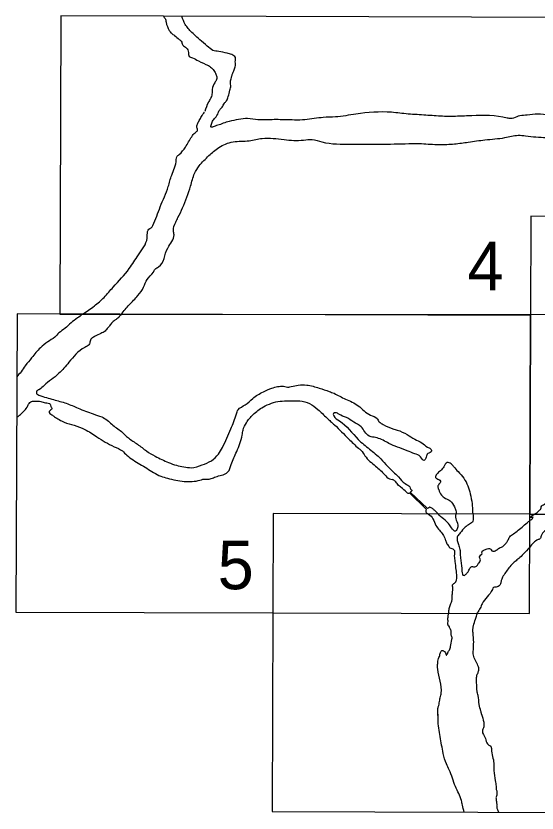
# Model space of a CAD drawing. Extents: x 3148686 to 3186545, y 916144 to 941516.
# Drawn here: x 3173455 to 3174711, y 918387 to 920308 of the extents above; entities that cross this region are included whole.
import ezdxf

# ---------------------------------------------------------------- set-up
doc = ezdxf.new("R2010")
doc.units = 0
doc.layers.add('V-ANNO-NPLT', color=7, linetype='Continuous')

msp = doc.modelspace()

# ---------------------------------------------------------------- linework, layer by layer
at = {"layer": 'V-ANNO-NPLT'}
for points in [[(3173561.2, 919589.7), (3174797, 919588.4), (3174800.4, 920304.2), (3173563.8, 920308.1), (3173561.2, 919589.7)], [(3174694, 919107.1), (3175931.7, 919104.3), (3175933, 919822.7), (3174696, 919825.5), (3174694, 919107.1)], [(3173455.5, 918871.6), (3174693.3, 918867.7), (3174695.3, 919586.1), (3173458.1, 919590), (3173455.5, 918871.6)], [(3174445.1, 919118.5), (3174403.9, 919158.6)], [(3174405.8, 919160.4), (3174447.5, 919121.2)], [(3174694, 919107.3), (3174075.2, 919109), (3174074.4, 918869.7)], [(3174072.9, 918390.6), (3175311.2, 918387.2), (3175312.8, 919105.6), (3174694, 919107.3)], [(3174074.4, 918869.7), (3174072.9, 918390.6)]]:
    msp.add_lwpolyline(points, dxfattribs=at)
for points in [[(3173810.2, 920307.1), (3173814.8, 920302.2), (3173817.4, 920292.8), (3173825.1, 920273.1), (3173830.2, 920266.2), (3173837.9, 920261.1), (3173849, 920251.7), (3173852.4, 920249.1), (3173855, 920244.8), (3173857.6, 920238), (3173861.9, 920234.6), (3173869.6, 920226), (3173871.3, 920220), (3173873, 920210.6), (3173880.7, 920207.2), (3173895.2, 920199.5), (3173919.2, 920188.3), (3173929.4, 920180.6), (3173935.4, 920172.1), (3173938.8, 920163.5), (3173938.8, 920154.9), (3173934.6, 920147.2), (3173928.6, 920131), (3173927.7, 920119.8), (3173924.3, 920108.7), (3173919.2, 920100.1), (3173910.6, 920077.9)], [(3173969.6, 920053.7), (3173955.1, 920049.6), (3173942.3, 920044.5), (3173935.4, 920042.8), (3173931.1, 920041), (3173927.7, 920040.2), (3173925.2, 920041), (3173926, 920044.5), (3173929.4, 920054.7), (3173935.4, 920062.5), (3173943.1, 920074.4), (3173946.5, 920082.1), (3173952.5, 920088.1), (3173957.7, 920097.6), (3173962.8, 920103.6), (3173967.1, 920113.8), (3173971.3, 920129.2), (3173973, 920140.4), (3173972.2, 920147.2), (3173973.9, 920156.6), (3173975.6, 920163.5), (3173978.2, 920170.3), (3173981.6, 920178), (3173984.2, 920188.3), (3173984.2, 920200.3), (3173984.2, 920208), (3173975.6, 920214.9), (3173964.5, 920218.3), (3173944, 920222.6), (3173930.3, 920225.1), (3173916.6, 920235.4), (3173898.6, 920250.8), (3173884.9, 920263.7), (3173874.7, 920273.1), (3173867, 920282.5), (3173863.6, 920287.6), (3173855.1, 920307.2)], [(3173616, 919589.5), (3173644.4, 919609.2), (3173667.9, 919629.9), (3173690, 919654.8), (3173728.6, 919699.1), (3173750.7, 919732.2), (3173771.5, 919772.3), (3173772.8, 919788.9), (3173775.6, 919794.5), (3173781.1, 919797.2), (3173785.3, 919802.8), (3173803.2, 919848.4), (3173822.6, 919896.8), (3173830.8, 919924.4), (3173837.8, 919942.4), (3173841.9, 919961.8), (3173843.3, 919968.7), (3173848.8, 919974.2), (3173864, 919992.2), (3173879.2, 920017.1), (3173887.5, 920026.7), (3173893, 920032.3), (3173891.6, 920039.2), (3173893, 920047.5), (3173897.1, 920055.8), (3173902.7, 920065.5), (3173909.6, 920076.5)], [(3174801.1, 920064.8), (3174774.8, 920066.2), (3174741.7, 920068.9), (3174712.7, 920071.7), (3174687.8, 920068.9), (3174669.9, 920067.5), (3174654.7, 920062), (3174647.8, 920060.6), (3174639.5, 920062), (3174553.9, 920067.5), (3174519.3, 920066.2), (3174483.4, 920066.2), (3174443.4, 920068.9), (3174400.6, 920071.7), (3174360.5, 920075.8), (3174274.9, 920071.7), (3174225.2, 920064.8), (3174196.2, 920063.4), (3174152, 920057.9), (3174102.2, 920057.9), (3174063.6, 920057.9), (3174038.7, 920057.9), (3174013.8, 920060.6), (3173969.6, 920053.7)], [(3173709.4, 919589.2), (3173728.6, 919612), (3173749.4, 919634.1), (3173763.2, 919654.8), (3173771.5, 919672.8), (3173786.6, 919690.8), (3173790.8, 919697.7), (3173799.1, 919703.2), (3173821.2, 919748.8), (3173836.4, 919780.6), (3173835, 919790.3), (3173840.5, 919811.1), (3173846, 919822.1), (3173857.1, 919845.6), (3173876.4, 919898.2), (3173886.1, 919928.6), (3173897.1, 919946.6), (3173920.6, 919971.4), (3173944.1, 919990.8), (3173978.6, 920004.6), (3174017.3, 920007.4), (3174049.1, 920012.9), (3174101.5, 920010.2), (3174148.5, 920008.8), (3174169.2, 920010.2), (3174192.7, 920004.6), (3174263.1, 919999.1), (3174340.5, 919999.1), (3174410.9, 920000.5), (3174433, 920000.5)], [(3174433, 920000.5), (3174475.1, 919998.4), (3174512.4, 919999.8), (3174545.6, 920003.9), (3174585.6, 920009.5), (3174634, 920015), (3174665.7, 920020.5), (3174683.7, 920019.1), (3174708.5, 920016.4), (3174733.4, 920015), (3174756.9, 920013.6), (3174773.5, 920012.2), (3174799, 920010.2)], [(3173616, 919589.5), (3173603.7, 919580.2), (3173588.4, 919568.5), (3173573.7, 919555.3), (3173559.1, 919544.3), (3173548.9, 919534.1), (3173532.1, 919522.4), (3173514.5, 919508.5), (3173493.3, 919484.3), (3173478, 919465.3), (3173467.8, 919450.7), (3173457.5, 919438.4)], [(3173709.4, 919589.2), (3173706, 919585.3), (3173703.1, 919581.6), (3173698.7, 919578), (3173692.1, 919573.6), (3173687.8, 919569.9), (3173684.1, 919565.6), (3173682.6, 919563.4), (3173676.8, 919556.8), (3173670.2, 919548.7), (3173660, 919542.9), (3173646.1, 919536.3), (3173638.1, 919531.2), (3173635.9, 919529), (3173634.4, 919524.6), (3173631.5, 919515.8), (3173621.2, 919509.2), (3173583.2, 919473.4), (3173558.4, 919446.3), (3173540.8, 919431.7), (3173523.3, 919417.8), (3173512.3, 919408.2), (3173505.8, 919404.6), (3173505, 919399.5), (3173505.8, 919397.3), (3173510.9, 919394.3), (3173546, 919383.4), (3173576.7, 919374.6), (3173605.2, 919362.9), (3173641.7, 919349), (3173662.2, 919341.7)], [(3173904.1, 919226.1), (3173926.8, 919236.3), (3173943.6, 919252.4), (3173953.1, 919268.5), (3173973.5, 919313.1), (3173986.7, 919349), (3173991.1, 919359.2), (3174007.9, 919370.9), (3174026.2, 919386.3), (3174051.7, 919402.4), (3174072.2, 919411.2), (3174086.1, 919414.8), (3174100, 919415.6), (3174106.5, 919414.1), (3174119, 919414.8), (3174135.8, 919418.5), (3174156.2, 919418.5), (3174186.2, 919411.2), (3174210.3, 919403.1), (3174222, 919398.7)], [(3174222, 919398.7), (3174249.8, 919384.8), (3174280.5, 919368.7), (3174309.7, 919346), (3174325.8, 919338), (3174330.9, 919330), (3174340.4, 919323.4), (3174363.8, 919313.1), (3174374.1, 919310.2), (3174398.2, 919299.2), (3174416.4, 919288.2), (3174433.3, 919279.5), (3174447.1, 919269.2), (3174454.4, 919264.8), (3174456.6, 919261.2), (3174455.9, 919257.5), (3174450.1, 919254.6), (3174444.9, 919248), (3174443.5, 919242.1), (3174439.1, 919237), (3174430.3, 919245.8), (3174416.4, 919253.1), (3174398.2, 919260.4), (3174374.8, 919269.2), (3174354.3, 919278), (3174325.8, 919291.2), (3174311.2, 919294.1), (3174306.8, 919295.6), (3174287.1, 919318.2), (3174269.5, 919329.2), (3174252, 919340.2), (3174233.7, 919348.2), (3174225.7, 919351.9), (3174220.6, 919350.4), (3174221.3, 919344.6), (3174235.2, 919332.1), (3174280.5, 919287.5), (3174307.5, 919264.1), (3174334.6, 919240.7), (3174351.4, 919222.4), (3174377.7, 919197.5)], [(3173457.6, 919340.4), (3173464.1, 919346), (3173472.9, 919354.1), (3173482.4, 919365.1), (3173486, 919372.4), (3173493.3, 919379), (3173501.4, 919379.7), (3173515.3, 919379), (3173527, 919376), (3173537.9, 919372.4), (3173539.4, 919367.3), (3173542.3, 919361.4), (3173535.7, 919354.8), (3173537.2, 919350.4), (3173542.3, 919346.8), (3173548.2, 919342.4)], [(3173905.6, 919191.7), (3173926, 919193.1), (3173937, 919197.5), (3173950.9, 919201.2), (3173966.2, 919209.2), (3173974.3, 919226.8), (3173987.4, 919258.2), (3174000.6, 919297.8), (3174002.8, 919310.2), (3174010.8, 919327.8), (3174026.9, 919347.5), (3174051.7, 919365.8), (3174091.9, 919379.7), (3174113.9, 919380.4), (3174139.4, 919380.4), (3174162.8, 919373.9), (3174183.3, 919359.9), (3174204.5, 919339.5), (3174223.5, 919322.6)], [(3173548.2, 919342.4), (3173571.5, 919329.2), (3173595.7, 919321.9), (3173621.2, 919311.7), (3173650.5, 919294.1), (3173692.1, 919270), (3173711.9, 919259.7), (3173722.8, 919249.5), (3173754.3, 919228.2), (3173787.2, 919207.8), (3173804.7, 919199), (3173820.8, 919193.9), (3173861, 919186.5), (3173899, 919189.5), (3173905.6, 919191.7)], [(3173662.2, 919341.7), (3173675.3, 919334.3), (3173686.3, 919324.1), (3173709.7, 919306.5), (3173726.5, 919291.2), (3173748.4, 919275.8), (3173770.3, 919259.7), (3173790.8, 919247.3), (3173823, 919231.9), (3173842, 919225.3), (3173860.2, 919221.7), (3173877.8, 919219.5), (3173904.1, 919226.1)], [(3174223.5, 919322.6), (3174257.1, 919289), (3174281.2, 919266.3), (3174287.1, 919261.2), (3174296.6, 919248), (3174322.2, 919223.1), (3174344.1, 919202.6), (3174355.8, 919192.4), (3174362.4, 919190.9)], [(3174711.3, 919111.6), (3174718.3, 919118), (3174720.4, 919120.1), (3174721.5, 919125.3), (3174728.8, 919131.6), (3174741.3, 919141), (3174754.9, 919154.6), (3174774.8, 919166.1), (3174793.6, 919180.7), (3174808.2, 919188.1), (3174830, 919195.3), (3174863.5, 919204.8), (3174880.3, 919211.1), (3174891.7, 919212.1), (3174910.6, 919219.4), (3174921, 919225.7), (3174933.5, 919227.8), (3174944, 919228.9), (3174974.3, 919244.5), (3174985.8, 919244.5), (3175000.4, 919250.8), (3175012.9, 919256), (3175018.2, 919256), (3175034.1, 919260.7), (3175063.1, 919273.8), (3175084, 919280.1), (3175097.5, 919282.2), (3175117.4, 919292.6), (3175136.2, 919295.8), (3175157.5, 919305.2), (3175167.5, 919307.3), (3175180.1, 919309.4), (3175194.7, 919312.5), (3175217.7, 919319.8), (3175235.4, 919326.1), (3175246.9, 919331.3), (3175255.3, 919329.3), (3175263.6, 919330.3), (3175284.5, 919337.6)], [(3174510, 919222.4), (3174504.1, 919229), (3174494.6, 919231.9), (3174486.6, 919221.7), (3174478.6, 919212.2), (3174469.8, 919204.1), (3174466.9, 919196.1), (3174474.9, 919190.9), (3174478.6, 919187.3), (3174476.4, 919181.4), (3174472, 919174.1), (3174474.2, 919166.8), (3174480.8, 919153.6), (3174490.3, 919145.6), (3174502, 919139.7), (3174512.2, 919125.1), (3174515.8, 919116.3), (3174516.6, 919110.4), (3174514.4, 919103.1), (3174518, 919090), (3174518.7, 919071.9), (3174514.5, 919066.5), (3174507.1, 919071.7), (3174500.6, 919082), (3174489.5, 919092.9), (3174475.6, 919105.3), (3174464.8, 919116.1), (3174459.4, 919120.8), (3174453.1, 919124), (3174447.5, 919121.2)], [(3174510, 919222.4), (3174521, 919210), (3174534.8, 919193.9), (3174544.3, 919175.6), (3174550.2, 919156.5), (3174554.6, 919132.4), (3174556, 919112.6), (3174557.5, 919096.5), (3174556.8, 919090.7), (3174548.7, 919083.4), (3174537.8, 919076.1), (3174526.1, 919062.2), (3174519.8, 919054.3), (3174518.8, 919043.9), (3174521.7, 919034.4), (3174525.3, 919022.6), (3174526.1, 919013.1), (3174526.1, 919008)], [(3174403.9, 919158.5), (3174400.7, 919156.9), (3174397.1, 919159.8), (3174383.9, 919171.5), (3174375.9, 919178.9), (3174369.3, 919186.9), (3174362.4, 919190.9)], [(3174377.7, 919197.5), (3174393.4, 919181.1), (3174404.4, 919173), (3174407.3, 919167.2), (3174409.5, 919165), (3174405.8, 919160.4)], [(3174445.1, 919118.5), (3174443.4, 919116.5), (3174443.1, 919113.4), (3174449.5, 919107.5), (3174460.2, 919096.5), (3174467.6, 919079.8), (3174484.4, 919058.5), (3174490.1, 919046.6), (3174493, 919038.5), (3174498.3, 919030), (3174501.1, 919026.7), (3174510, 919022.6), (3174511.5, 919006.6)], [(3174535.8, 918959.7), (3174541.5, 918964.3), (3174546, 918970.3), (3174551.2, 918979.3), (3174554.2, 918981.5), (3174557.9, 918980.8), (3174561.7, 918980.8), (3174567.7, 918984.5), (3174571.4, 918990.5), (3174574.4, 918995), (3174574.4, 918999.5), (3174572.9, 919003.3), (3174572.9, 919004.8), (3174575.9, 919009.3), (3174578.9, 919013.8), (3174578.2, 919016.8), (3174581.2, 919019.8), (3174588.7, 919022.8), (3174598.4, 919024.3), (3174600.6, 919021.3), (3174604.4, 919018.3), (3174612.6, 919020.5), (3174620.1, 919025.8), (3174625.3, 919028), (3174636.6, 919037.8), (3174641.1, 919044.5), (3174645.6, 919052.8), (3174654.6, 919060.2), (3174665.8, 919068.5), (3174690.5, 919089.5), (3174696.5, 919094), (3174700.2, 919097), (3174701.7, 919100), (3174698, 919099.2), (3174695, 919099.2), (3174693.5, 919099.2), (3174697.2, 919102.2), (3174701.7, 919105.2), (3174711.3, 919111.6)], [(3174807.6, 919111.6), (3174801.3, 919108.2), (3174799.1, 919104.5), (3174793.1, 919100), (3174761.6, 919082), (3174729.4, 919066.2), (3174725.7, 919063.2), (3174721.9, 919057.2), (3174720.5, 919052.8), (3174719.7, 919049.8), (3174713.7, 919046), (3174693.5, 919028), (3174677.8, 919010.8), (3174667.3, 919001), (3174658.3, 918993.5), (3174650.1, 918986), (3174633.6, 918964.3), (3174626.8, 918953), (3174624.6, 918945.5), (3174623.8, 918941.8), (3174620.1, 918935.1), (3174614.9, 918932.1), (3174611.1, 918931.3), (3174606.6, 918930.6), (3174603.6, 918926.1), (3174578.9, 918891.6), (3174574.4, 918881.1), (3174567.8, 918869.8)], [(3174511.5, 919006.6), (3174513.3, 918993.6), (3174515.7, 918973.7), (3174516.7, 918965.1), (3174516.9, 918952.8), (3174515.5, 918945.5), (3174514.7, 918943.3)], [(3174526.1, 919008), (3174527.9, 918993.9), (3174529.4, 918982), (3174530.7, 918965.7), (3174532.7, 918960.8), (3174535.9, 918959.7)], [(3174498.4, 918869.5), (3174499.5, 918880.3), (3174502.5, 918890.1), (3174505.5, 918897.6), (3174507, 918913.3), (3174507.8, 918921.6), (3174508.5, 918929.8), (3174507.8, 918937.3), (3174513.8, 918942.5), (3174514.7, 918943.3)], [(3174498.4, 918869.5), (3174496.6, 918862.6), (3174496.1, 918858.1), (3174495.7, 918853.5), (3174496.1, 918849), (3174495.7, 918842.6), (3174496.6, 918839.9), (3174499.3, 918836.2), (3174500.2, 918833.9), (3174502.1, 918830.8), (3174503.4, 918827.1), (3174503.4, 918822.6), (3174503.4, 918818.9), (3174503.9, 918814.8), (3174505.7, 918810.7), (3174505.3, 918805.2), (3174502.1, 918788.9), (3174499.8, 918779.3)], [(3174558, 918783.1), (3174558.5, 918798.9), (3174557.1, 918821.2), (3174556.7, 918830.8), (3174558, 918838.5), (3174562.6, 918854.4), (3174565.8, 918864.5), (3174568, 918870.4)], [(3174577.7, 918625.1), (3174575.8, 918633.1), (3174571.7, 918649), (3174569.4, 918670.4), (3174566.7, 918681.3), (3174565.8, 918696.8), (3174565.3, 918709.6), (3174566.2, 918718.7), (3174566.7, 918721), (3174568.5, 918723.7), (3174569, 918725.1), (3174570.8, 918733.7), (3174567.6, 918745.6), (3174564.4, 918751.5), (3174558.5, 918764.3), (3174557.6, 918771.1), (3174557.6, 918777), (3174558, 918783.8)], [(3174472.5, 918622.1), (3174472, 918632.2), (3174472.5, 918639.4), (3174474.3, 918646.7), (3174476.6, 918659), (3174479.3, 918671.3), (3174480.2, 918676.3), (3174472, 918734.2), (3174471.6, 918741), (3174472, 918749.7), (3174474.8, 918762.4), (3174477, 918766.5), (3174477, 918769.7), (3174478.4, 918773.8), (3174479.8, 918777), (3174482, 918778.8), (3174483.9, 918778.8), (3174487, 918777.5), (3174489.3, 918775.6), (3174491.6, 918771.1), (3174492.1, 918768.8), (3174492.5, 918767.9), (3174496.1, 918773.4), (3174499.8, 918779.3)], [(3174535.5, 918389.4), (3174531.5, 918406.4), (3174529, 918417.3), (3174514.7, 918451), (3174499.6, 918491.4), (3174492.8, 918505.6), (3174485.3, 918530.9), (3174477.7, 918571.3), (3174472.7, 918612.5), (3174472.7, 918625.1)], [(3174577.7, 918625.1), (3174582.7, 918606.6), (3174582.7, 918594.8), (3174579.4, 918584.7), (3174586.9, 918567.1), (3174592, 918553.6), (3174595.3, 918551.1), (3174599.5, 918548.5), (3174601.2, 918541), (3174607.1, 918507.3), (3174607.2, 918489.5), (3174610.5, 918465.3), (3174612.4, 918452.1), (3174613, 918444.2)], [(3174613, 918444.2), (3174614, 918440.8), (3174614.2, 918437), (3174614.2, 918432.6), (3174614, 918429.4), (3174613.5, 918427.6), (3174612.4, 918425.3), (3174612.4, 918422.2), (3174612.9, 918417.4), (3174613.5, 918413.3), (3174614, 918409.2), (3174614.5, 918406.9), (3174614.7, 918405.3), (3174614.5, 918405)], [(3174614.5, 918405), (3174614.2, 918401), (3174615.1, 918397.6), (3174616.7, 918393.2), (3174618.4, 918389.5)]]:
    msp.add_spline(points, degree=3, dxfattribs=at)

# ---------------------------------------------------------------- texts
for s, p in [('4', (3174543.6, 919646.9)), ('5', (3173941.5, 918926.6))]:
    msp.add_text(s, height=117, rotation=359.9396, dxfattribs=at).set_placement(p)

doc.saveas('drawing.dxf')
